(* Logix 5000 project; controller EVR_Heat vendor 1 type 14 code 217 rev 35.11; software revision 35.00 *)

TASK MainTask (continuous, watchdog 500 ms) : MainProgram

MODULES
   Local : vendor 1 type 14 code 217 (5069 0, rev 35.11)
      EVR : ETHERNET-MODULE (Ethernet 192.168.2.50, rev 1.1, Output RPI 10 ms)   // EVR Map Heat
END_MODULES

TYPE ADM_Bits :
STRUCT
   Requested : ADM_Bits_Request;
   Status : ADM_Bits_Status;
END_STRUCT
END_TYPE

TYPE ADM_Bits_Request :
STRUCT
   AcknowledgeSetupValuesChanged : BOOL;
   AcknowledgeCounterValuesChanged : BOOL;
END_STRUCT
END_TYPE

TYPE ADM_Bits_Status :
STRUCT
   SetupValuesChanged : BOOL;
   CounterValuesChanged : BOOL;
END_STRUCT
END_TYPE

TYPE ADM_Time_Date :
STRUCT
   Current : Structer_Date_Time;
   Requested : Structer_Date_Time;
   SendNewTime : BOOL;
   SendNewDate : BOOL;
END_STRUCT
END_TYPE

TYPE Data_Exchange :
STRUCT
   Status : Data_Exchange_Variables;
   Request : Data_Exchange_Variables;
END_STRUCT
END_TYPE

TYPE Data_Exchange_Variables :
STRUCT
   Element : INT;
   Value : DINT;
END_STRUCT
END_TYPE

TYPE Error_LookUp :
STRUCT
   Status : Error_LookUp_Status;
   Request : Error_LookUp_Request;
END_STRUCT
END_TYPE

TYPE Error_LookUp_Request :
STRUCT
   ModuleToLookUp : SINT;
END_STRUCT
END_TYPE

TYPE Error_LookUp_Status :
STRUCT
   Alarms : DINT;
   Deviations : DINT;
   Advisories : DINT;
   LookUpModule : SINT;
   ModuleErrorState : Errors_Module_Booleans;
END_STRUCT
END_TYPE

TYPE Error_Present_Booleans :
STRUCT
   AlarmPresent : BOOL;
   DeviationPresent : BOOL;
   AdvisoriesPresent : BOOL;
END_STRUCT
END_TYPE

TYPE Errors_Module_Booleans :
STRUCT
   RedMcm : Error_Present_Booleans;
   BlueMcm : Error_Present_Booleans;
   RedTank : Error_Present_Booleans;
   BlueTank : Error_Present_Booleans;
   Voltex : Error_Present_Booleans;
END_STRUCT
END_TYPE

TYPE EVR_ADM :
STRUCT
   Bits : ADM_Bits;
   Date_Time : ADM_Time_Date;
END_STRUCT
END_TYPE

TYPE EVR_System :
STRUCT
   Bits : System_Bits;
   ErrorLookUp : Error_LookUp;
   Information : System_Information;
   Recipes : Recipes;
   DataExchange : Data_Exchange;
   HeartbeatMonitoring : Equipment_Heartbeat_Monitoring;
END_STRUCT
END_TYPE

TYPE EVR_Voltex :
STRUCT
   Bits : Voltex_Bits;
END_STRUCT
END_TYPE

TYPE HEAT_Bits_System :
STRUCT
   Status : HEAT_Bits_System_Status;
   Request : HEAT_Bits_System_Requested;
END_STRUCT
END_TYPE

TYPE HEAT_Bits_System_Requested :
STRUCT
   HeatOn : BOOL;
   HeatOff : BOOL;
   HeatSetback : BOOL;
   AcknowledgeClearErrors : BOOL;
   ResetSystemOffReason : BOOL;
   ResetIdleTimer : BOOL;
END_STRUCT
END_TYPE

TYPE HEAT_Bits_System_Status :
STRUCT
   HeartbeatToPlc : BOOL;
   SystemActive : BOOL;   // System On
   ZonesActive : BOOL;   // Zone(s) Active
   ZonesWarmingUp : BOOL;   // Zone(s) Warming Up
   ZonesHeaksoaking : BOOL;   // Zone(s) are Heatsoaking
   ZonesAtTemperature : BOOL;   // All Zone(s) are at Temperature
   ZonesInSetback : BOOL;   // All Zone(s) are in Setback Mode
   NoSystemAlarmsPresent : BOOL;
   NoSystemDeviationsPresent : BOOL;
   NoSystemAdvisoriesPresent : BOOL;
   NoZonesAlarmsPresent : BOOL;   // No Zone(s) Alarms are Present
   NoZonesDeviationsPresent : BOOL;   // No Zone(s) Deviations are Present
   NoZonesAdvisoriesPresent : BOOL;   // No Zone(s) Advisories are Present
   Shutdown : HEAT_Bits_System_Status_Shutdown;   // Reason for heat being shutdown
END_STRUCT
END_TYPE

TYPE HEAT_Bits_System_Status_Shutdown :
STRUCT
   FromADM : BOOL;
   ADMRedKeyPressed : BOOL;
   PumpIdleTimeout : BOOL;
   AlarmDetected : BOOL;
   InternalGracoNetworkLost : BOOL;
   PlcConnectionLost : BOOL;
   PlcRelinquishedControl : BOOL;
END_STRUCT
END_TYPE

TYPE HEAT_Bits_Zone_Enabled_Request :
STRUCT
   Cmd : HEAT_Zone_Struct_BOOL;
   Strobe : BOOL;   // Send to the Heat Controller
   Feedback : HEAT_Setup_Parameters_Feedback;
END_STRUCT
END_TYPE

TYPE HEAT_Bits_Zone_Status :
STRUCT
   Installed : HEAT_Zone_Struct_BOOL;
   Active : HEAT_Zone_Struct_BOOL;   // Heat is On
   AlarmPresent : HEAT_Zone_Struct_BOOL;
END_STRUCT
END_TYPE

TYPE HEAT_Bits_Zones :
STRUCT
   Status : HEAT_Bits_Zone_Status;
END_STRUCT
END_TYPE

TYPE HEAT_Data :
STRUCT
   System : HEAT_System;
   Zone : HEAT_Zone_Information;
   DataExchange : Data_Exchange;
   Errors : HEAT_Errors;
   HeartbeatMonitoring : Equipment_Heartbeat_Monitoring;
END_STRUCT
END_TYPE

TYPE HEAT_Errors :
STRUCT
   System : HEAT_Errors_System;
END_STRUCT
END_TYPE

TYPE HEAT_Errors_System :
STRUCT
   Alarms : DINT;
   Deviations : DINT;
   Advisories : DINT;
END_STRUCT
END_TYPE

TYPE HEAT_Errors_Zone_Struct :
STRUCT
   Alarms : INT;
   Deviations : INT;
   Advisories : INT;
END_STRUCT
END_TYPE

TYPE HEAT_Individual_Zone_Actual_Status :
STRUCT
   State : HEAT_Individual_Zone_Heat_States;
   Temperature : DINT;   // XXX.X deg C
   HeatSoakTimeRemaining : INT;   // XXXX seconds
   CurrentUsage : SINT;   // XX.X Amps
   DutyCycle : SINT;   // XXX %
END_STRUCT
END_TYPE

TYPE HEAT_Individual_Zone_Heat_States :
STRUCT
   WarmingUp : BOOL;
   HeatSoak : BOOL;
   AtTemperature : BOOL;
   Setback : BOOL;
   DeviationAdvisoryPresent : BOOL;
   AlarmPresent : BOOL;
END_STRUCT
END_TYPE

TYPE HEAT_Individual_Zone_Setup_Status :
STRUCT
   ZoneType : SINT;   // 0=HOSE, 1=VALVE, 2=MANIFOLD, 3=PGM, 4=FLOWMETER, 5=PRESS REG, 6=BLANKET, 7=OTHER, 8=MONITOR ONLY
   Setpoint : INT;   // XXX deg C
   Setback : INT;   // XXX deg C
   HeatSoak : SINT;   // XXX minutes
END_STRUCT
END_TYPE

TYPE HEAT_Individual_Zone_Status :
STRUCT
   Setup : HEAT_Individual_Zone_Setup_Status;
   Actual : HEAT_Individual_Zone_Actual_Status;
END_STRUCT
END_TYPE

TYPE HEAT_Information_Status :
STRUCT
   LongestHeatSoakRemaining : INT;   // XXXX seconds
   IdleTimeoutCountdown : INT;   // XXXX seconds
END_STRUCT
END_TYPE

TYPE HEAT_Information_System :
STRUCT
   Status : HEAT_Information_Status;
END_STRUCT
END_TYPE

TYPE HEAT_Information_Zones :
STRUCT
   ActualTemperature : HEAT_Zone_Struct_INT;   // XXXX.X deg C
END_STRUCT
END_TYPE

TYPE HEAT_Setup_Parameters :
STRUCT
   Setpoint : HEAT_Setup_Parameters_INT;
   Setback : HEAT_Setup_Parameters_INT;
   Heatsoak : HEAT_Setup_Parameters_INT;
   Enabled : HEAT_Bits_Zone_Enabled_Request;
END_STRUCT
END_TYPE

TYPE HEAT_Setup_Parameters_Feedback :
STRUCT
   Accepted : BOOL;
   Rejected : BOOL;
END_STRUCT
END_TYPE

TYPE HEAT_Setup_Parameters_INT :
STRUCT
   Feedback : HEAT_Setup_Parameters_Feedback;
   RequestValue : INT;
   Update : HEAT_Zone_Struct_BOOL;
   Strobe : BOOL;   // Send to Heat Controller
END_STRUCT
END_TYPE

TYPE HEAT_System :
STRUCT
   Bits : HEAT_Bits_System;
   Information : HEAT_Information_System;
END_STRUCT
END_TYPE

TYPE HEAT_Zone_Individual_Information :
STRUCT
   Bits : HEAT_Bits_Zones;
   Information : HEAT_Information_Zones;
END_STRUCT
END_TYPE

TYPE HEAT_Zone_Information :
STRUCT
   Information : HEAT_Zone_Individual_Information;
   SetupParameters : HEAT_Setup_Parameters;
   Multiplexer : HEAT_Zone_Multiplexer;
END_STRUCT
END_TYPE

TYPE HEAT_Zone_Multiplexer :
STRUCT
   RequestZone : SINT;
   ZoneInformation : HEAT_Zone_Multiplexer_Information;
END_STRUCT
END_TYPE

TYPE HEAT_Zone_Multiplexer_Information :
STRUCT
   ActiveNumber : SINT;   // Zone information displayed
   State : HEAT_Individual_Zone_Heat_States;
   SoakTimeRemaining : INT;   // XXXX seconds
   CurrentUsage : INT;   // XX.X Amps
   DutyCycle : INT;   // XXX %
   SetpointTemperature : INT;   // XXX deg C
   SetbackTemperature : INT;   // XXX deg C
   HeatSoakSetTime : SINT;   // XXX minutes
   Profile : SINT;   // 0 = Hose 1 = Valve 2 = Manifold 3 = PGM 4 = Flowmeter 5= Press Reg
   Alarms : INT;
   Deviations : INT;
   Advisories : INT;
END_STRUCT
END_TYPE

TYPE HEAT_Zone_Struct_BOOL :
STRUCT
   Zone1 : BOOL;
   Zone2 : BOOL;
   Zone3 : BOOL;
   Zone4 : BOOL;
   Zone5 : BOOL;
   Zone6 : BOOL;
   Zone7 : BOOL;
   Zone8 : BOOL;
   Zone9 : BOOL;
   Zone10 : BOOL;
   Zone11 : BOOL;
   Zone12 : BOOL;
   Zone13 : BOOL;
   Zone14 : BOOL;
   Zone15 : BOOL;
   Zone16 : BOOL;
END_STRUCT
END_TYPE

TYPE HEAT_Zone_Struct_INT :
STRUCT
   Zone1 : INT;
   Zone2 : INT;
   Zone3 : INT;
   Zone4 : INT;
   Zone5 : INT;
   Zone6 : INT;
   Zone7 : INT;
   Zone8 : INT;
   Zone9 : INT;
   Zone10 : INT;
   Zone11 : INT;
   Zone12 : INT;
   Zone13 : INT;
   Zone14 : INT;
   Zone15 : INT;
   Zone16 : INT;
END_STRUCT
END_TYPE

TYPE Recipe_Active_Status :
STRUCT
   AmountDispensed : DINT;   // XXXX.XX cc
   ShotSize : DINT;   // XXXX.XX cc
   Flowrate : INT;   // XXXX.XX cc/sec
   ShotCalibartion : INT;   // -/+ XX.XX cc
   DispenseType : SINT;   // 0=operator, 1=shot
   ShotTimeRemaining : INT;   // XXXX.X seconds
   Recipe : SINT;
END_STRUCT
END_TYPE

TYPE Recipe_Gateway_Request :
STRUCT
   Flowrate : INT;   // XXX.XX cc/sec
   ShotSize : DINT;   // XXXX.XX cc
   DispenseType : SINT;   // 0 = operator, 1 = shot
   Recipe : SINT;
END_STRUCT
END_TYPE

TYPE Recipe_Lookup :
STRUCT
   Request : Recipe_Lookup_Request;
   Status : Recipe_Lookup_Status;
END_STRUCT
END_TYPE

TYPE Recipe_Lookup_Request :
STRUCT
   LookUpRecipe : SINT;
END_STRUCT
END_TYPE

TYPE Recipe_Lookup_Status :
STRUCT
   ActiveNumber : SINT;
   ShotSize : DINT;   // XXXX.XX cc
   Flowrate : INT;   // XXX.XX cc/sec
   Calibration : INT;   // -/+ XX.XX cc
   DipsenseType : SINT;   // 0=operator, 1=shot
END_STRUCT
END_TYPE

TYPE Recipes :
STRUCT
   Active : Recipe_Active_Status;
   Gateway : Recipe_Gateway_Request;
   Lookup : Recipe_Lookup;
END_STRUCT
END_TYPE

TYPE Structer_Date :   // Will house the information for the date
STRUCT
   Month : SINT;
   Year : SINT;
   Day : SINT;
END_STRUCT
END_TYPE

TYPE Structer_Date_Time :   // Will house the information for the date & time in military time
STRUCT
   Date : Structer_Date;
   Time : Structer_Time;
END_STRUCT
END_TYPE

TYPE Structer_Tank_Levels :
STRUCT
   Unknown : BOOL;
   Low : BOOL;
   Middle : BOOL;
   High : BOOL;
END_STRUCT
END_TYPE

TYPE Structer_Time :   // Will house the information for the time in Military Time
STRUCT
   Hours : SINT;
   Minutes : SINT;
   Seconds : SINT;
END_STRUCT
END_TYPE

TYPE System :
STRUCT
   EVR : EVR_System;
   ADM : EVR_ADM;
   Voltex : EVR_Voltex;
   Tanks : TankStands;
   Heat : HEAT_Data;
END_STRUCT
END_TYPE

TYPE System_Bits :
STRUCT
   Status : System_Bits_Status;
   Requested : System_Bits_Request;
END_STRUCT
END_TYPE

TYPE System_Bits_Request :
STRUCT
   SystemEnable : BOOL;
   PLCLockout : BOOL;
   OperatorShotDispense : BOOL;
   CancelShot : BOOL;
   Purge : BOOL;
   BasePurge : BOOL;
   Depressurization : BOOL;
   Park : BOOL;
   AcknowledgeAllErrors : BOOL;
   GatewayRecipeLockout : BOOL;
   CancelGelShot : BOOL;
   Recirculation : BOOL;
END_STRUCT
END_TYPE

TYPE System_Bits_Status :
STRUCT
   HeartbeatToPLC : BOOL;
   SystemOn : BOOL;
   PlcLockoutIsActive : BOOL;
   SystemReady : BOOL;
   NoSystemAlarmsPresent : BOOL;
   NoSystemDeviationsPresent : BOOL;
   NoSystemAdvisoriesPresent : BOOL;
   RecipeIsDispensing : BOOL;
   DispenseValveIsOpened : BOOL;
   SystemIsPurging : BOOL;
   SystemIsBasePurging : BOOL;
   SystemIsDepressurizing : BOOL;
   SystemIsParking : BOOL;
   SystemIsParked : BOOL;
   RecipeIsValid : BOOL;
   GaetwayRecipeLockoutActive : BOOL;
   GelShotIsDispensing : BOOL;
   GelShotIsAlarming : BOOL;
   SystemIsRecirculating : BOOL;
   DispenseValveIsOpen : Valves;
   AutoRecirculationValvesIsOpen : Valves;
END_STRUCT
END_TYPE

TYPE System_Information :
STRUCT
   Request : System_Information_Request;
   Status : System_Information_Status;
END_STRUCT
END_TYPE

TYPE System_Information_Request :
STRUCT
   Ratio : INT;   // XX.XX : 1.00
   RatioOffset : INT;   // -/+XX.XX
END_STRUCT
END_TYPE

TYPE System_Information_Status :
STRUCT
   OuletPressure_Red : INT;   // XX.XX bar
   OutletPressure_Blue : INT;   // XX.XX bar
   InletPressure_Red : INT;   // XX.XX bar
   InletPressure_Blue : INT;   // XX.XX bar
   Ratio : INT;   // XX.XX : 1.00
   RatioOffset : INT;   // -/+ XX.XX
   CombinedFlow : INT;   // XX.XX cc/sec
   GelTimeRemainingBeforeShot : INT;   // XXXX seconds
   RecirculationTimeRemaining : INT;   // XXXX seconds
END_STRUCT
END_TYPE

TYPE TanksStands_Individual :
STRUCT
   Request : TankStand_Bits_Request;
   Status : TankStand_Bits_Status;
END_STRUCT
END_TYPE

TYPE TankStand_Bits :
STRUCT
   Request : TankStand_Bits_Request;
   Status : TankStand_Bits_Status;
END_STRUCT
END_TYPE

TYPE TankStand_Bits_Request :
STRUCT
   Fill : BOOL;
END_STRUCT
END_TYPE

TYPE TankStand_Bits_Status :
STRUCT
   IsFilling : BOOL;
   Levels : Structer_Tank_Levels;
END_STRUCT
END_TYPE

TYPE TankStands :
STRUCT
   Red : TanksStands_Individual;
   Blue : TanksStands_Individual;
END_STRUCT
END_TYPE

TYPE Valves :
STRUCT
   A : BOOL;
   B : BOOL;
END_STRUCT
END_TYPE

TYPE Voltex_Bits :
STRUCT
   Request : Voltex_Bits_Request;
   Status : Voltex_Bits_Status;
END_STRUCT
END_TYPE

TYPE Voltex_Bits_Request :
STRUCT
   MotorOn : BOOL;
   AirInjectionOpen : BOOL;
END_STRUCT
END_TYPE

TYPE Voltex_Bits_Status :
STRUCT
   MotorIsRunning : BOOL;
   DispenseWaitingSpeedReached : BOOL;
   AtTargetSpeed : BOOL;
   AirInjectionValveOpen : BOOL;
END_STRUCT
END_TYPE

ADD_ON_INSTRUCTION Equipment_Heartbeat_Monitoring   (* revision 1.0, vendor Graco *)
// This logic will monitoring for the heatbeat, if it is gone for a specific amount of time, then set an disconnect bit
VAR_INPUT
   EquipmentHeartbeat : BOOL; {access None, required}   // Is the actual status of the heartbeat that is being monitored
END_VAR
VAR_OUTPUT
   EquipmentDisconnected : BOOL; {access None, visible}   // Lets the world outside the function know that the equipment is offline
END_VAR
VAR_INPUT
   OfflineTimeout : ALIAS FOR ElapsedTime_Timer.PRE; {access None, required}   // XXXX ms
   StopMonitoringTimer : BOOL; {access None, required}   // Variable that can be used to stop the heartbeat logic from erroring out
END_VAR
VAR
   LowSideMonitor_Counter : COUNTER; {access None}
   HighSideMonitor_Counter : COUNTER; {access None}
   HeartbeatFailiure : BOOL; {access None}
   ElapsedTime_Timer : TIMER; {access None}
END_VAR

ROUTINE Logic   (* ladder *)
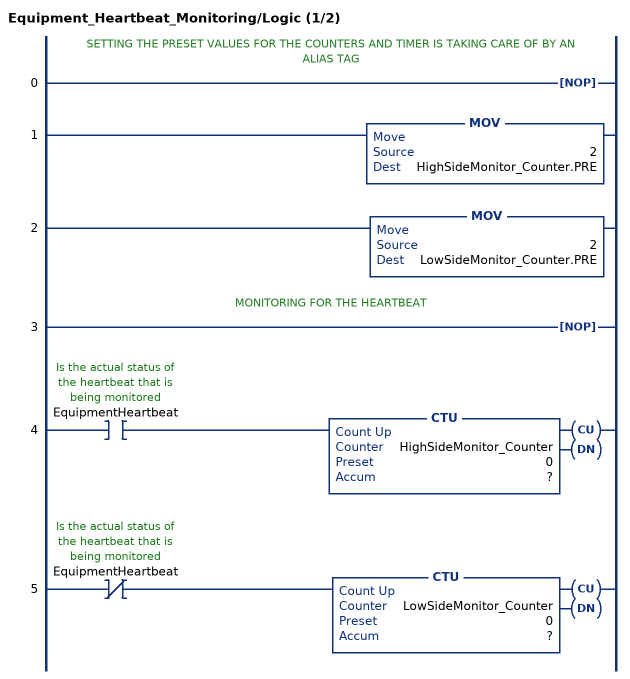
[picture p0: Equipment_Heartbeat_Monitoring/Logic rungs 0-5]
   // SETTING THE PRESET VALUES FOR THE COUNTERS AND TIMER IS TAKING CARE OF BY AN ALIAS TAG
   0: NOP();
   1: MOV(2,HighSideMonitor_Counter.PRE);
   2: MOV(2,LowSideMonitor_Counter.PRE);
   // MONITORING FOR THE HEARTBEAT
   3: NOP();
   4: XIC(EquipmentHeartbeat)CTU(HighSideMonitor_Counter,?,?);
   5: XIO(EquipmentHeartbeat)CTU(LowSideMonitor_Counter,?,?);
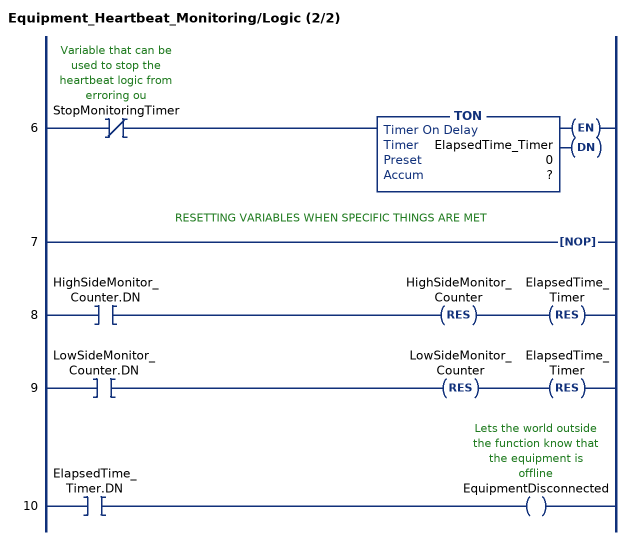
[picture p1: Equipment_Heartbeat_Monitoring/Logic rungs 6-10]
   6: XIO(StopMonitoringTimer)TON(ElapsedTime_Timer,?,?);
   // RESETTING VARIABLES WHEN SPECIFIC THINGS ARE MET
   7: NOP();
   8: XIC(HighSideMonitor_Counter.DN)RES(HighSideMonitor_Counter)RES(ElapsedTime_Timer);
   9: XIC(LowSideMonitor_Counter.DN)RES(LowSideMonitor_Counter)RES(ElapsedTime_Timer);
   10: XIC(ElapsedTime_Timer.DN)OTE(EquipmentDisconnected);
END_ROUTINE
END_ADD_ON_INSTRUCTION

VAR_GLOBAL   (* controller tags *)
   EVR_System_Data : System;
        .Heat.Zone.Multiplexer.ZoneInformation.Alarms.3   // T8A_
        .Heat.Errors.System.Alarms.10   // CCFX
        .Heat.Zone.Multiplexer.ZoneInformation.Alarms.0   // T4A_
        .Heat.Errors.System.Deviations.5   // T9TX
        .Heat.Errors.System.Alarms.0   // CBH1
        .Heat.Zone.Multiplexer.ZoneInformation.Alarms.1   // T4A_
        .Heat.Zone.Multiplexer.ZoneInformation.Alarms.2   // T1A_
        .Heat.Zone.Multiplexer.ZoneInformation.Alarms.4   // T9A_
        .Heat.Zone.Multiplexer.ZoneInformation.Alarms.5   // A4A_
        .Heat.Errors.System.Alarms.11   // V6H1
        .Heat.Errors.System.Alarms.1   // CBH2
        .Heat.Errors.System.Alarms.12   // V4H1
        .Heat.Errors.System.Alarms.9   // CBGX
        .Heat.Errors.System.Alarms.8   // CABX
        .Heat.Errors.System.Alarms.14   // T4TX
        .Heat.Errors.System.Alarms.20   // V6H2
        .Heat.Zone.Multiplexer.ZoneInformation.Alarms.6   // A1A_
        .Heat.Errors.System.Advisories.0   // MGFX
        .Heat.Zone.Multiplexer.ZoneInformation.Alarms.7   // A8A_
        .Heat.Errors.System.Deviations.1   // V2H1
        .Heat.Zone.Multiplexer.ZoneInformation.Alarms.8   // A7A_
        .Heat.Errors.System.Alarms.21   // V4H2
        .Heat.Zone.Multiplexer.ZoneInformation.Alarms.9   // T6A_
        .Heat.Errors.System.Deviations.17   // V2H2
        .Heat.Zone.Multiplexer.ZoneInformation.Advisories.0   // T3A_
        .Heat.Errors.System.Deviations.2   // A2VX
        .Heat.Errors.System.Deviations.3   // A3VX
        .Heat.Zone.Multiplexer.ZoneInformation.Advisories.1   // T3A_
        .Heat.Zone.Multiplexer.ZoneInformation.Advisories.2   // T2A_
        .Heat.Zone.Multiplexer.ZoneInformation.Advisories.4   // A3A_
        .Heat.Errors.System.Deviations.4   // T3TX
        .Heat.Zone.Multiplexer.ZoneInformation.Advisories.5   // A2A_
        .Heat.Errors.System.Deviations.6   // T6TX
END_VAR

PROGRAM MainProgram   (* main routine MainRoutine *)

ROUTINE EVR_Inputs   (* ladder *)
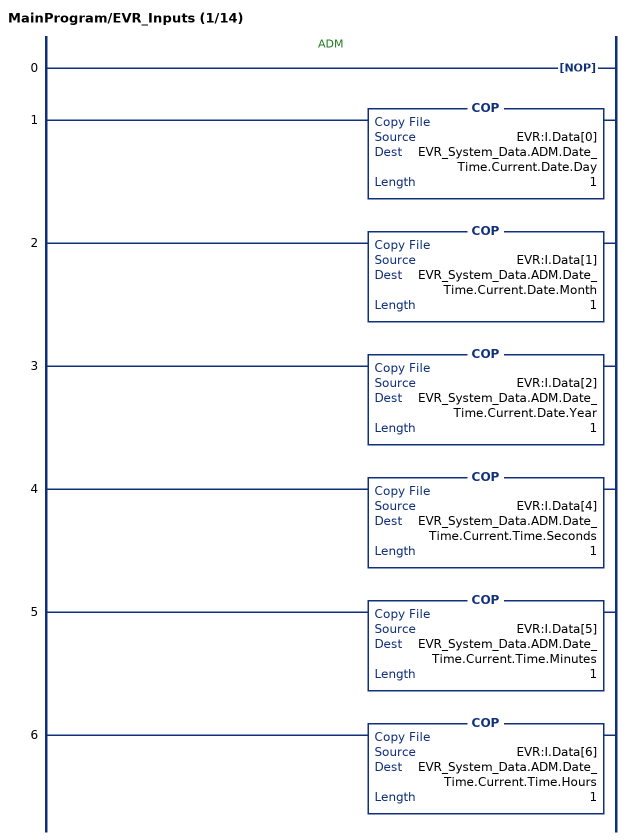
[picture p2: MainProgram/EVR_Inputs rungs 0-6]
   // ADM
   0: NOP();
   1: COP(EVR:I.Data[0],EVR_System_Data.ADM.Date_Time.Current.Date.Day,1);
   2: COP(EVR:I.Data[1],EVR_System_Data.ADM.Date_Time.Current.Date.Month,1);
   3: COP(EVR:I.Data[2],EVR_System_Data.ADM.Date_Time.Current.Date.Year,1);
   4: COP(EVR:I.Data[4],EVR_System_Data.ADM.Date_Time.Current.Time.Seconds,1);
   5: COP(EVR:I.Data[5],EVR_System_Data.ADM.Date_Time.Current.Time.Minutes,1);
   6: COP(EVR:I.Data[6],EVR_System_Data.ADM.Date_Time.Current.Time.Hours,1);
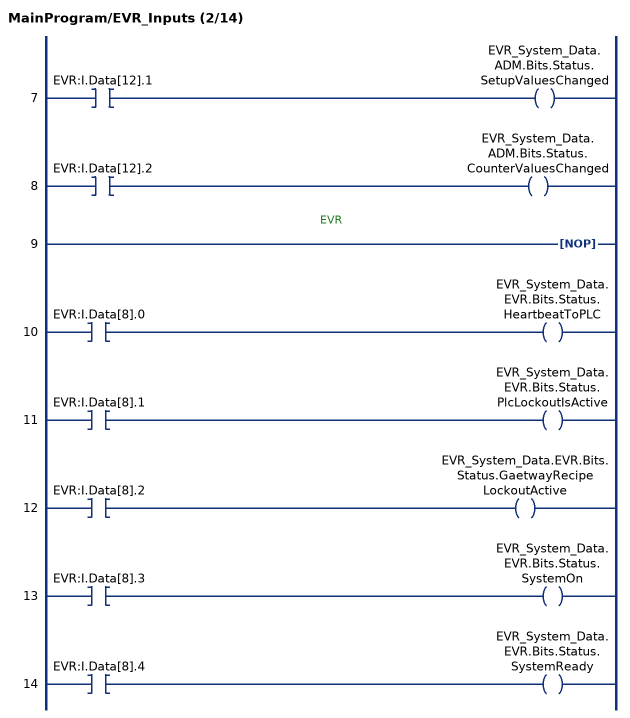
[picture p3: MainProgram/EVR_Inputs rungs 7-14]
   7: XIC(EVR:I.Data[12].1)OTE(EVR_System_Data.ADM.Bits.Status.SetupValuesChanged);
   8: XIC(EVR:I.Data[12].2)OTE(EVR_System_Data.ADM.Bits.Status.CounterValuesChanged);
   // EVR
   9: NOP();
   10: XIC(EVR:I.Data[8].0)OTE(EVR_System_Data.EVR.Bits.Status.HeartbeatToPLC);
   11: XIC(EVR:I.Data[8].1)OTE(EVR_System_Data.EVR.Bits.Status.PlcLockoutIsActive);
   12: XIC(EVR:I.Data[8].2)OTE(EVR_System_Data.EVR.Bits.Status.GaetwayRecipeLockoutActive);
   13: XIC(EVR:I.Data[8].3)OTE(EVR_System_Data.EVR.Bits.Status.SystemOn);
   14: XIC(EVR:I.Data[8].4)OTE(EVR_System_Data.EVR.Bits.Status.SystemReady);
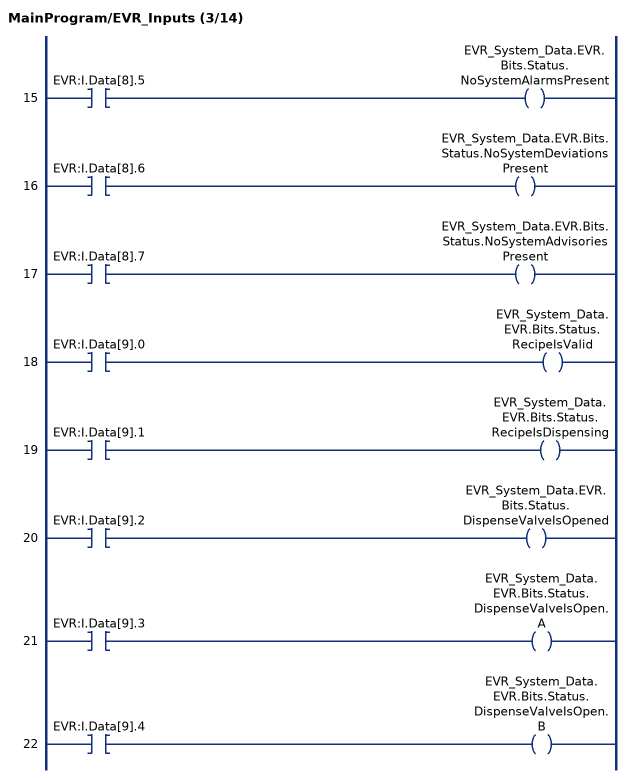
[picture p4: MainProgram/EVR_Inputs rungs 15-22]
   15: XIC(EVR:I.Data[8].5)OTE(EVR_System_Data.EVR.Bits.Status.NoSystemAlarmsPresent);
   16: XIC(EVR:I.Data[8].6)OTE(EVR_System_Data.EVR.Bits.Status.NoSystemDeviationsPresent);
   17: XIC(EVR:I.Data[8].7)OTE(EVR_System_Data.EVR.Bits.Status.NoSystemAdvisoriesPresent);
   18: XIC(EVR:I.Data[9].0)OTE(EVR_System_Data.EVR.Bits.Status.RecipeIsValid);
   19: XIC(EVR:I.Data[9].1)OTE(EVR_System_Data.EVR.Bits.Status.RecipeIsDispensing);
   20: XIC(EVR:I.Data[9].2)OTE(EVR_System_Data.EVR.Bits.Status.DispenseValveIsOpened);
   21: XIC(EVR:I.Data[9].3)OTE(EVR_System_Data.EVR.Bits.Status.DispenseValveIsOpen.A);
   22: XIC(EVR:I.Data[9].4)OTE(EVR_System_Data.EVR.Bits.Status.DispenseValveIsOpen.B);
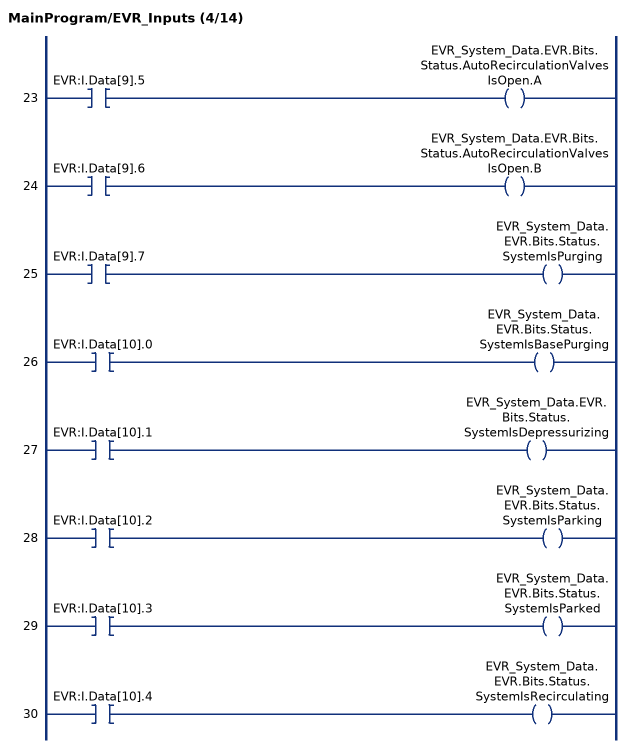
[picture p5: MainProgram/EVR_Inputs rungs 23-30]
   23: XIC(EVR:I.Data[9].5)OTE(EVR_System_Data.EVR.Bits.Status.AutoRecirculationValvesIsOpen.A);
   24: XIC(EVR:I.Data[9].6)OTE(EVR_System_Data.EVR.Bits.Status.AutoRecirculationValvesIsOpen.B);
   25: XIC(EVR:I.Data[9].7)OTE(EVR_System_Data.EVR.Bits.Status.SystemIsPurging);
   26: XIC(EVR:I.Data[10].0)OTE(EVR_System_Data.EVR.Bits.Status.SystemIsBasePurging);
   27: XIC(EVR:I.Data[10].1)OTE(EVR_System_Data.EVR.Bits.Status.SystemIsDepressurizing);
   28: XIC(EVR:I.Data[10].2)OTE(EVR_System_Data.EVR.Bits.Status.SystemIsParking);
   29: XIC(EVR:I.Data[10].3)OTE(EVR_System_Data.EVR.Bits.Status.SystemIsParked);
   30: XIC(EVR:I.Data[10].4)OTE(EVR_System_Data.EVR.Bits.Status.SystemIsRecirculating);
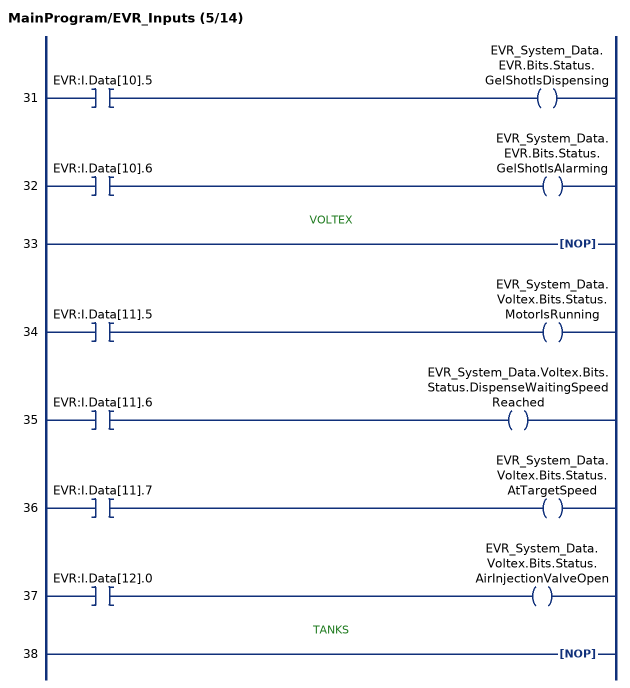
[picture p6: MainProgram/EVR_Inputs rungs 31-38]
   31: XIC(EVR:I.Data[10].5)OTE(EVR_System_Data.EVR.Bits.Status.GelShotIsDispensing);
   32: XIC(EVR:I.Data[10].6)OTE(EVR_System_Data.EVR.Bits.Status.GelShotIsAlarming);
   // VOLTEX
   33: NOP();
   34: XIC(EVR:I.Data[11].5)OTE(EVR_System_Data.Voltex.Bits.Status.MotorIsRunning);
   35: XIC(EVR:I.Data[11].6)OTE(EVR_System_Data.Voltex.Bits.Status.DispenseWaitingSpeedReached);
   36: XIC(EVR:I.Data[11].7)OTE(EVR_System_Data.Voltex.Bits.Status.AtTargetSpeed);
   37: XIC(EVR:I.Data[12].0)OTE(EVR_System_Data.Voltex.Bits.Status.AirInjectionValveOpen);
   // TANKS
   38: NOP();
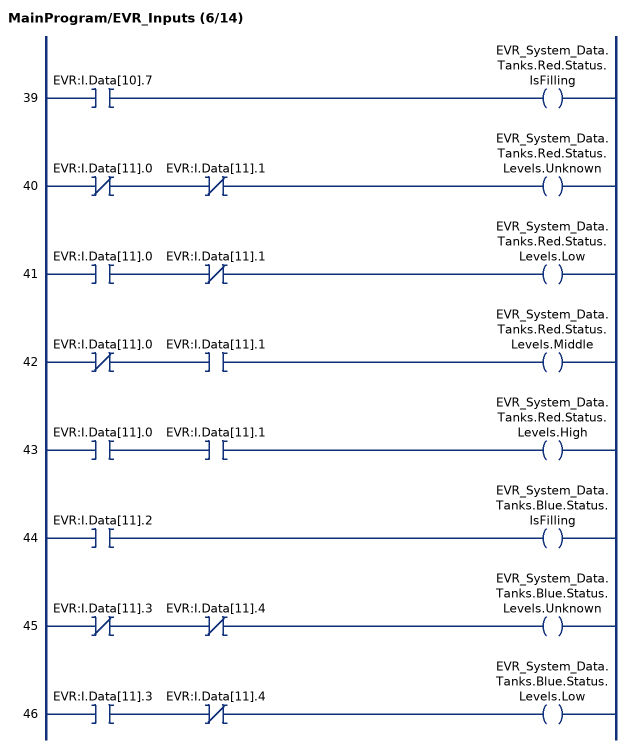
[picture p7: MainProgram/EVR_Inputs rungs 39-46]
   39: XIC(EVR:I.Data[10].7)OTE(EVR_System_Data.Tanks.Red.Status.IsFilling);
   40: XIO(EVR:I.Data[11].0)XIO(EVR:I.Data[11].1)OTE(EVR_System_Data.Tanks.Red.Status.Levels.Unknown);
   41: XIC(EVR:I.Data[11].0)XIO(EVR:I.Data[11].1)OTE(EVR_System_Data.Tanks.Red.Status.Levels.Low);
   42: XIO(EVR:I.Data[11].0)XIC(EVR:I.Data[11].1)OTE(EVR_System_Data.Tanks.Red.Status.Levels.Middle);
   43: XIC(EVR:I.Data[11].0)XIC(EVR:I.Data[11].1)OTE(EVR_System_Data.Tanks.Red.Status.Levels.High);
   44: XIC(EVR:I.Data[11].2)OTE(EVR_System_Data.Tanks.Blue.Status.IsFilling);
   45: XIO(EVR:I.Data[11].3)XIO(EVR:I.Data[11].4)OTE(EVR_System_Data.Tanks.Blue.Status.Levels.Unknown);
   46: XIC(EVR:I.Data[11].3)XIO(EVR:I.Data[11].4)OTE(EVR_System_Data.Tanks.Blue.Status.Levels.Low);
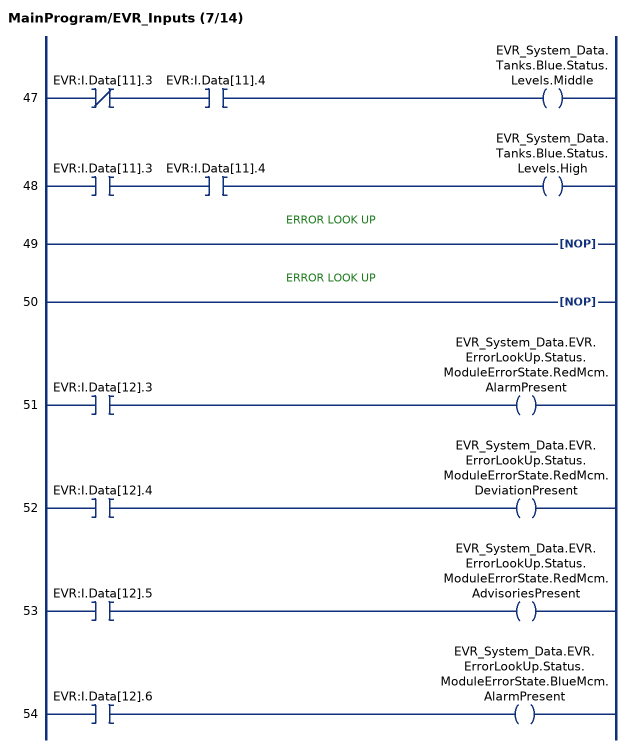
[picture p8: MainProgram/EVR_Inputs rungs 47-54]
   47: XIO(EVR:I.Data[11].3)XIC(EVR:I.Data[11].4)OTE(EVR_System_Data.Tanks.Blue.Status.Levels.Middle);
   48: XIC(EVR:I.Data[11].3)XIC(EVR:I.Data[11].4)OTE(EVR_System_Data.Tanks.Blue.Status.Levels.High);
   // ERROR LOOK UP
   49: NOP();
   // ERROR LOOK UP
   50: NOP();
   51: XIC(EVR:I.Data[12].3)OTE(EVR_System_Data.EVR.ErrorLookUp.Status.ModuleErrorState.RedMcm.AlarmPresent);
   52: XIC(EVR:I.Data[12].4)OTE(EVR_System_Data.EVR.ErrorLookUp.Status.ModuleErrorState.RedMcm.DeviationPresent);
   53: XIC(EVR:I.Data[12].5)OTE(EVR_System_Data.EVR.ErrorLookUp.Status.ModuleErrorState.RedMcm.AdvisoriesPresent);
   54: XIC(EVR:I.Data[12].6)OTE(EVR_System_Data.EVR.ErrorLookUp.Status.ModuleErrorState.BlueMcm.AlarmPresent);
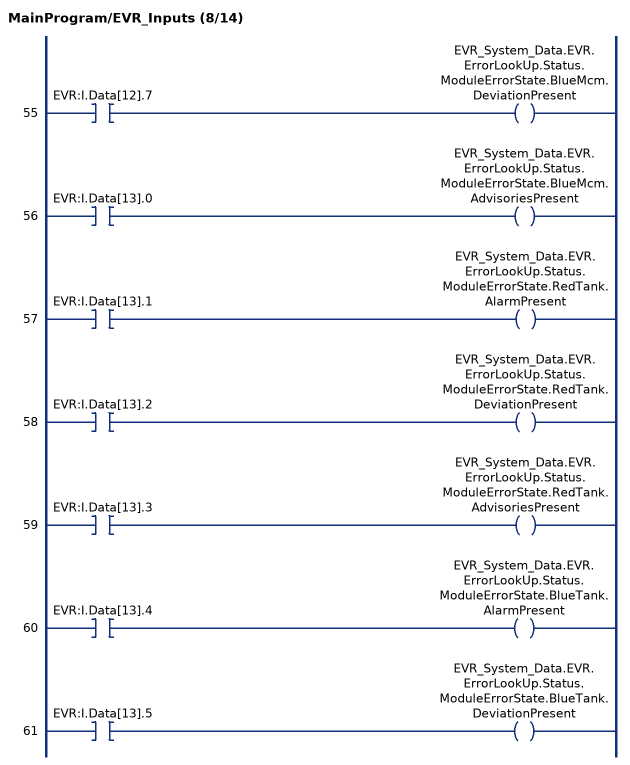
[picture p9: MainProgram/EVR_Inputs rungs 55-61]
   55: XIC(EVR:I.Data[12].7)OTE(EVR_System_Data.EVR.ErrorLookUp.Status.ModuleErrorState.BlueMcm.DeviationPresent);
   56: XIC(EVR:I.Data[13].0)OTE(EVR_System_Data.EVR.ErrorLookUp.Status.ModuleErrorState.BlueMcm.AdvisoriesPresent);
   57: XIC(EVR:I.Data[13].1)OTE(EVR_System_Data.EVR.ErrorLookUp.Status.ModuleErrorState.RedTank.AlarmPresent);
   58: XIC(EVR:I.Data[13].2)OTE(EVR_System_Data.EVR.ErrorLookUp.Status.ModuleErrorState.RedTank.DeviationPresent);
   59: XIC(EVR:I.Data[13].3)OTE(EVR_System_Data.EVR.ErrorLookUp.Status.ModuleErrorState.RedTank.AdvisoriesPresent);
   60: XIC(EVR:I.Data[13].4)OTE(EVR_System_Data.EVR.ErrorLookUp.Status.ModuleErrorState.BlueTank.AlarmPresent);
   61: XIC(EVR:I.Data[13].5)OTE(EVR_System_Data.EVR.ErrorLookUp.Status.ModuleErrorState.BlueTank.DeviationPresent);
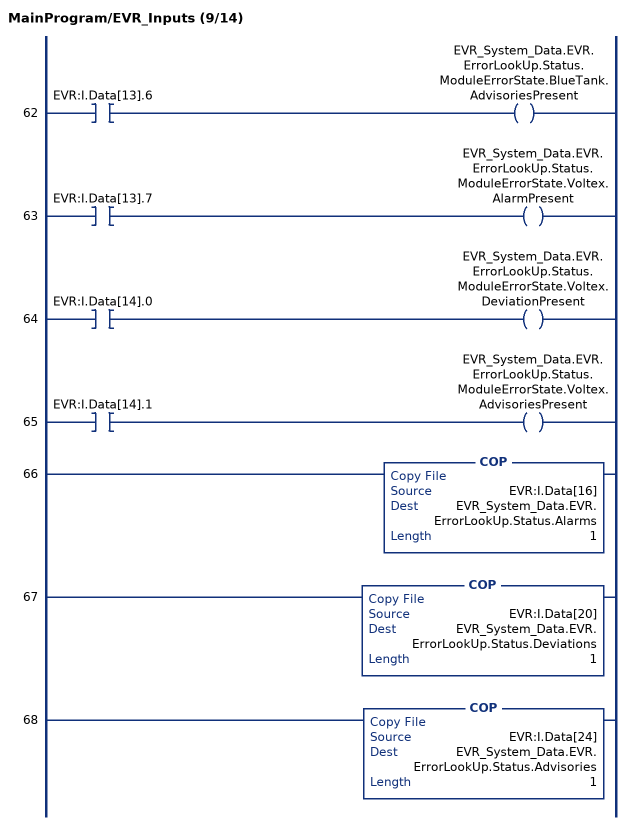
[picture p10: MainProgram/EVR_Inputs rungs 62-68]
   62: XIC(EVR:I.Data[13].6)OTE(EVR_System_Data.EVR.ErrorLookUp.Status.ModuleErrorState.BlueTank.AdvisoriesPresent);
   63: XIC(EVR:I.Data[13].7)OTE(EVR_System_Data.EVR.ErrorLookUp.Status.ModuleErrorState.Voltex.AlarmPresent);
   64: XIC(EVR:I.Data[14].0)OTE(EVR_System_Data.EVR.ErrorLookUp.Status.ModuleErrorState.Voltex.DeviationPresent);
   65: XIC(EVR:I.Data[14].1)OTE(EVR_System_Data.EVR.ErrorLookUp.Status.ModuleErrorState.Voltex.AdvisoriesPresent);
   66: COP(EVR:I.Data[16],EVR_System_Data.EVR.ErrorLookUp.Status.Alarms,1);
   67: COP(EVR:I.Data[20],EVR_System_Data.EVR.ErrorLookUp.Status.Deviations,1);
   68: COP(EVR:I.Data[24],EVR_System_Data.EVR.ErrorLookUp.Status.Advisories,1);
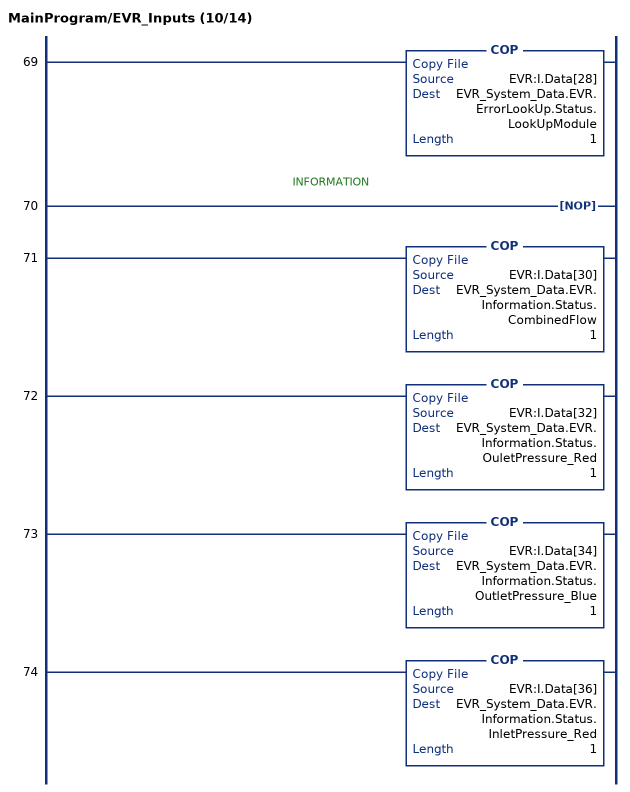
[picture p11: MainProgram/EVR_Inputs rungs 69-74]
   69: COP(EVR:I.Data[28],EVR_System_Data.EVR.ErrorLookUp.Status.LookUpModule,1);
   // INFORMATION
   70: NOP();
   71: COP(EVR:I.Data[30],EVR_System_Data.EVR.Information.Status.CombinedFlow,1);
   72: COP(EVR:I.Data[32],EVR_System_Data.EVR.Information.Status.OuletPressure_Red,1);
   73: COP(EVR:I.Data[34],EVR_System_Data.EVR.Information.Status.OutletPressure_Blue,1);
   74: COP(EVR:I.Data[36],EVR_System_Data.EVR.Information.Status.InletPressure_Red,1);
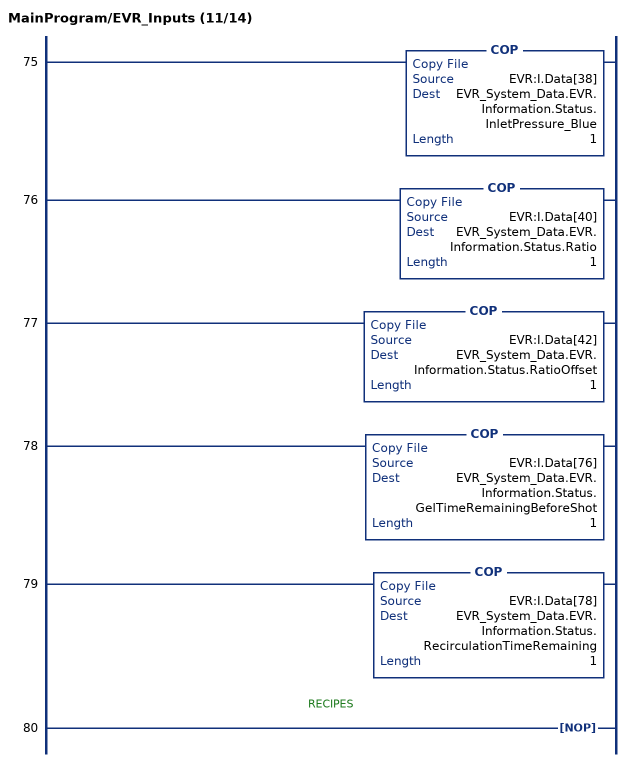
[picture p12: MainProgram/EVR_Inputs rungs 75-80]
   75: COP(EVR:I.Data[38],EVR_System_Data.EVR.Information.Status.InletPressure_Blue,1);
   76: COP(EVR:I.Data[40],EVR_System_Data.EVR.Information.Status.Ratio,1);
   77: COP(EVR:I.Data[42],EVR_System_Data.EVR.Information.Status.RatioOffset,1);
   78: COP(EVR:I.Data[76],EVR_System_Data.EVR.Information.Status.GelTimeRemainingBeforeShot,1);
   79: COP(EVR:I.Data[78],EVR_System_Data.EVR.Information.Status.RecirculationTimeRemaining,1);
   // RECIPES
   80: NOP();
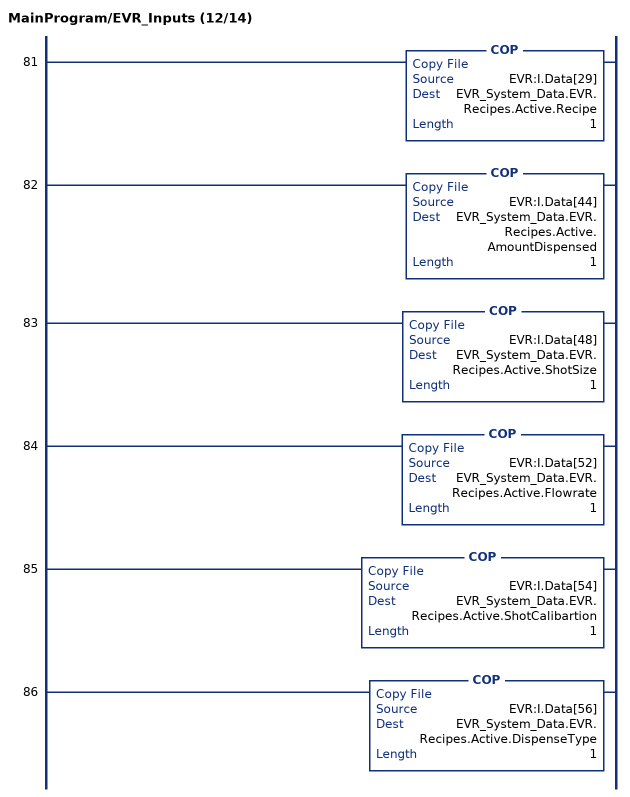
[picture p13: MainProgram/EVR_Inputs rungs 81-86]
   81: COP(EVR:I.Data[29],EVR_System_Data.EVR.Recipes.Active.Recipe,1);
   82: COP(EVR:I.Data[44],EVR_System_Data.EVR.Recipes.Active.AmountDispensed,1);
   83: COP(EVR:I.Data[48],EVR_System_Data.EVR.Recipes.Active.ShotSize,1);
   84: COP(EVR:I.Data[52],EVR_System_Data.EVR.Recipes.Active.Flowrate,1);
   85: COP(EVR:I.Data[54],EVR_System_Data.EVR.Recipes.Active.ShotCalibartion,1);
   86: COP(EVR:I.Data[56],EVR_System_Data.EVR.Recipes.Active.DispenseType,1);
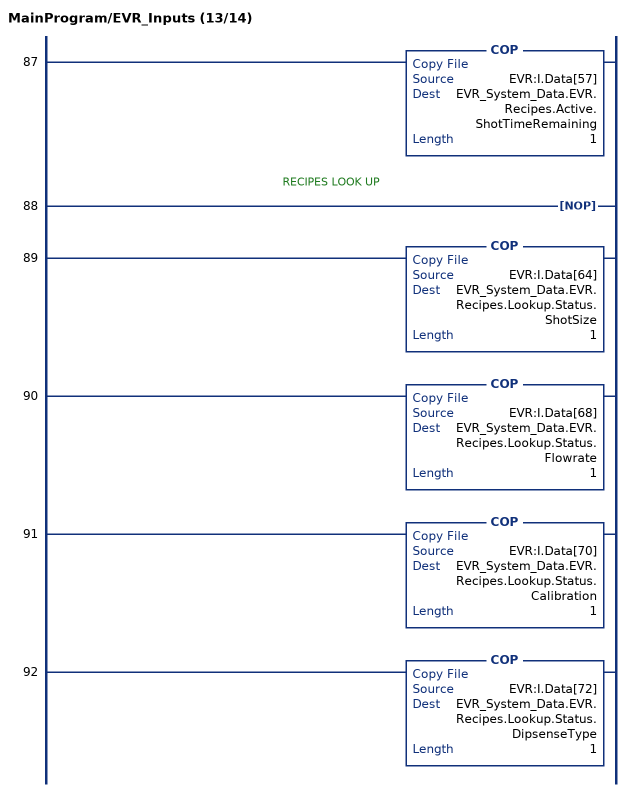
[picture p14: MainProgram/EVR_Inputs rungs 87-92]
   87: COP(EVR:I.Data[57],EVR_System_Data.EVR.Recipes.Active.ShotTimeRemaining,1);
   // RECIPES LOOK UP
   88: NOP();
   89: COP(EVR:I.Data[64],EVR_System_Data.EVR.Recipes.Lookup.Status.ShotSize,1);
   90: COP(EVR:I.Data[68],EVR_System_Data.EVR.Recipes.Lookup.Status.Flowrate,1);
   91: COP(EVR:I.Data[70],EVR_System_Data.EVR.Recipes.Lookup.Status.Calibration,1);
   92: COP(EVR:I.Data[72],EVR_System_Data.EVR.Recipes.Lookup.Status.DipsenseType,1);
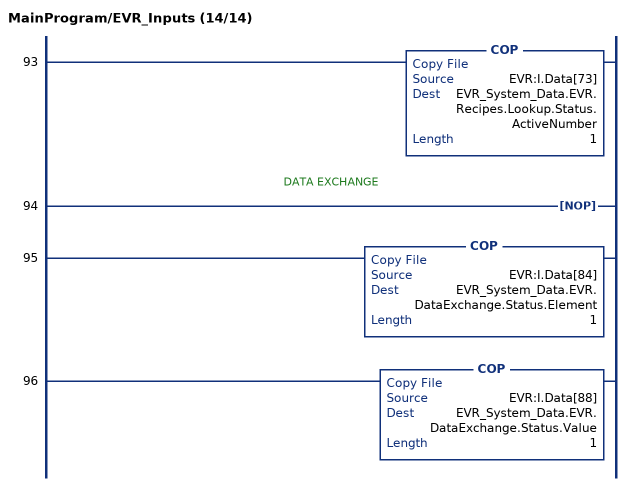
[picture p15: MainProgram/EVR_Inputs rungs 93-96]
   93: COP(EVR:I.Data[73],EVR_System_Data.EVR.Recipes.Lookup.Status.ActiveNumber,1);
   // DATA EXCHANGE
   94: NOP();
   95: COP(EVR:I.Data[84],EVR_System_Data.EVR.DataExchange.Status.Element,1);
   96: COP(EVR:I.Data[88],EVR_System_Data.EVR.DataExchange.Status.Value,1);
END_ROUTINE

ROUTINE EVR_Outputs   (* ladder *)
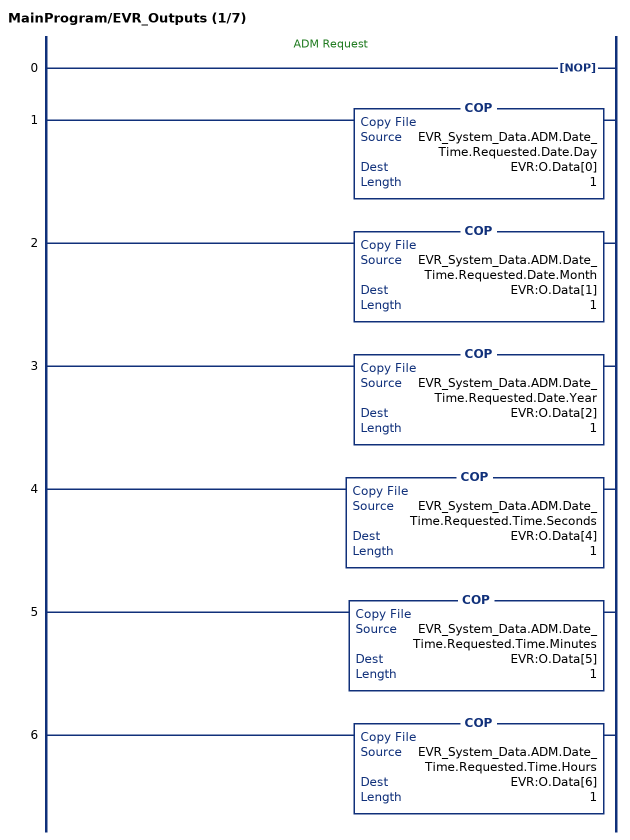
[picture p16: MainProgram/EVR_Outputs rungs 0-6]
   // ADM Request
   0: NOP();
   1: COP(EVR_System_Data.ADM.Date_Time.Requested.Date.Day,EVR:O.Data[0],1);
   2: COP(EVR_System_Data.ADM.Date_Time.Requested.Date.Month,EVR:O.Data[1],1);
   3: COP(EVR_System_Data.ADM.Date_Time.Requested.Date.Year,EVR:O.Data[2],1);
   4: COP(EVR_System_Data.ADM.Date_Time.Requested.Time.Seconds,EVR:O.Data[4],1);
   5: COP(EVR_System_Data.ADM.Date_Time.Requested.Time.Minutes,EVR:O.Data[5],1);
   6: COP(EVR_System_Data.ADM.Date_Time.Requested.Time.Hours,EVR:O.Data[6],1);
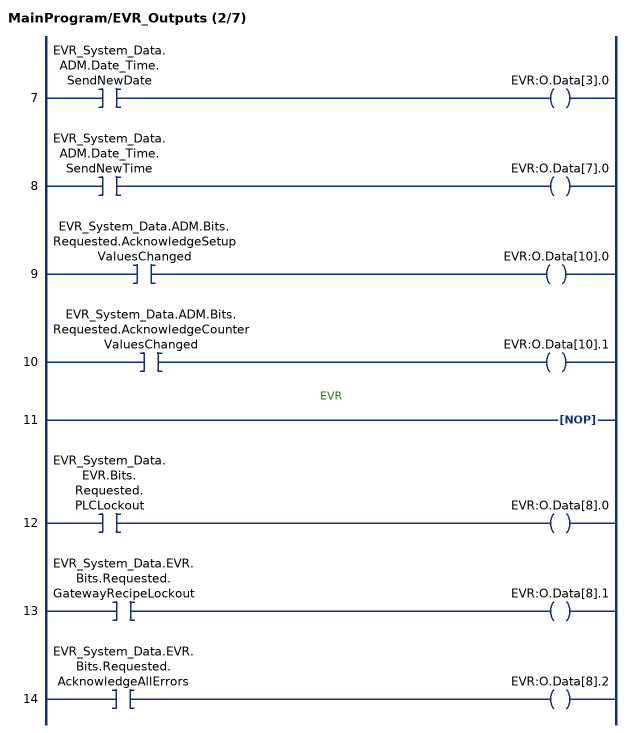
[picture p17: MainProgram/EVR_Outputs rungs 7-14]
   7: XIC(EVR_System_Data.ADM.Date_Time.SendNewDate)OTE(EVR:O.Data[3].0);
   8: XIC(EVR_System_Data.ADM.Date_Time.SendNewTime)OTE(EVR:O.Data[7].0);
   9: XIC(EVR_System_Data.ADM.Bits.Requested.AcknowledgeSetupValuesChanged)OTE(EVR:O.Data[10].0);
   10: XIC(EVR_System_Data.ADM.Bits.Requested.AcknowledgeCounterValuesChanged)OTE(EVR:O.Data[10].1);
   // EVR
   11: NOP();
   12: XIC(EVR_System_Data.EVR.Bits.Requested.PLCLockout)OTE(EVR:O.Data[8].0);
   13: XIC(EVR_System_Data.EVR.Bits.Requested.GatewayRecipeLockout)OTE(EVR:O.Data[8].1);
   14: XIC(EVR_System_Data.EVR.Bits.Requested.AcknowledgeAllErrors)OTE(EVR:O.Data[8].2);
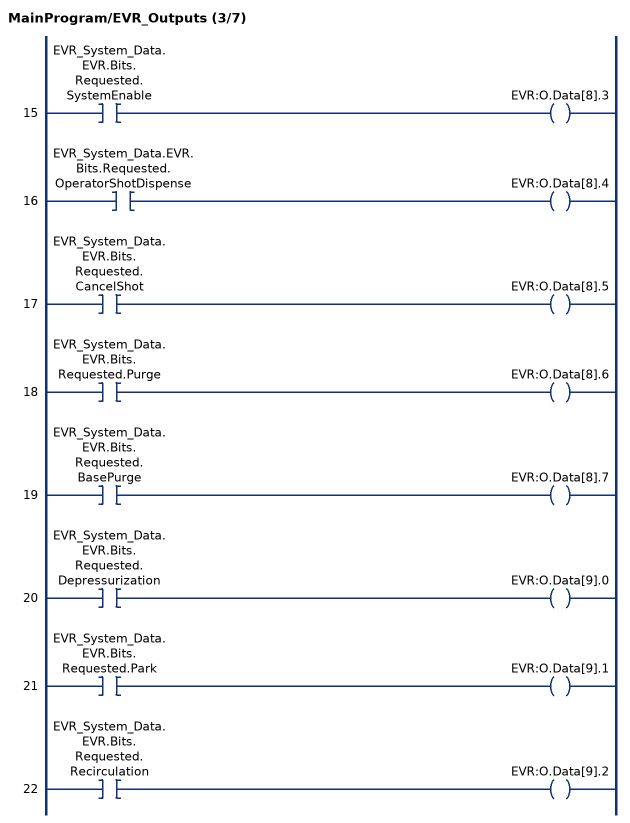
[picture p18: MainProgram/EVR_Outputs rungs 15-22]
   15: XIC(EVR_System_Data.EVR.Bits.Requested.SystemEnable)OTE(EVR:O.Data[8].3);
   16: XIC(EVR_System_Data.EVR.Bits.Requested.OperatorShotDispense)OTE(EVR:O.Data[8].4);
   17: XIC(EVR_System_Data.EVR.Bits.Requested.CancelShot)OTE(EVR:O.Data[8].5);
   18: XIC(EVR_System_Data.EVR.Bits.Requested.Purge)OTE(EVR:O.Data[8].6);
   19: XIC(EVR_System_Data.EVR.Bits.Requested.BasePurge)OTE(EVR:O.Data[8].7);
   20: XIC(EVR_System_Data.EVR.Bits.Requested.Depressurization)OTE(EVR:O.Data[9].0);
   21: XIC(EVR_System_Data.EVR.Bits.Requested.Park)OTE(EVR:O.Data[9].1);
   22: XIC(EVR_System_Data.EVR.Bits.Requested.Recirculation)OTE(EVR:O.Data[9].2);
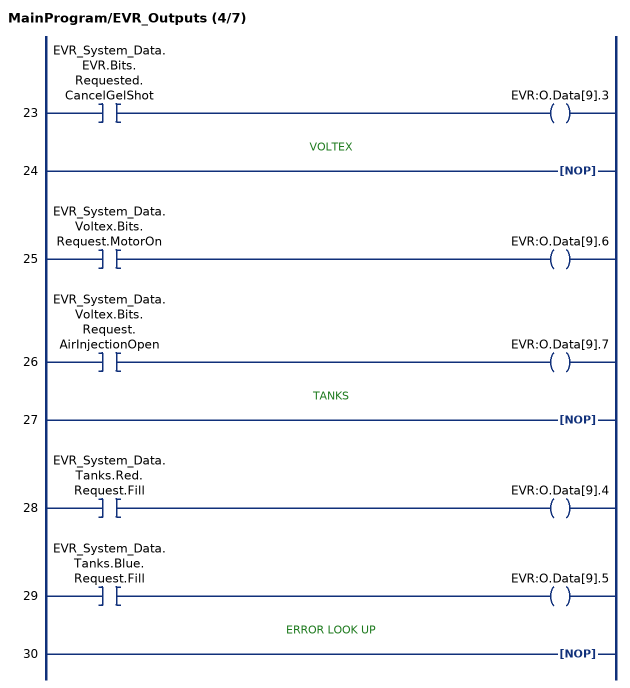
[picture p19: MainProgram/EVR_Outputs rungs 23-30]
   23: XIC(EVR_System_Data.EVR.Bits.Requested.CancelGelShot)OTE(EVR:O.Data[9].3);
   // VOLTEX
   24: NOP();
   25: XIC(EVR_System_Data.Voltex.Bits.Request.MotorOn)OTE(EVR:O.Data[9].6);
   26: XIC(EVR_System_Data.Voltex.Bits.Request.AirInjectionOpen)OTE(EVR:O.Data[9].7);
   // TANKS
   27: NOP();
   28: XIC(EVR_System_Data.Tanks.Red.Request.Fill)OTE(EVR:O.Data[9].4);
   29: XIC(EVR_System_Data.Tanks.Blue.Request.Fill)OTE(EVR:O.Data[9].5);
   // ERROR LOOK UP
   30: NOP();
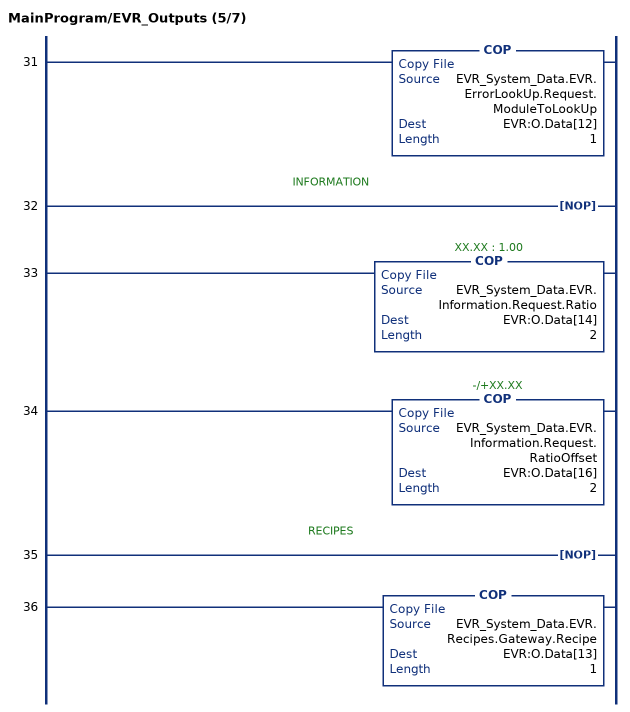
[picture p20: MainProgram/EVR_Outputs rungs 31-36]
   31: COP(EVR_System_Data.EVR.ErrorLookUp.Request.ModuleToLookUp,EVR:O.Data[12],1);
   // INFORMATION
   32: NOP();
   33: COP(EVR_System_Data.EVR.Information.Request.Ratio,EVR:O.Data[14],2);
   34: COP(EVR_System_Data.EVR.Information.Request.RatioOffset,EVR:O.Data[16],2);
   // RECIPES
   35: NOP();
   36: COP(EVR_System_Data.EVR.Recipes.Gateway.Recipe,EVR:O.Data[13],1);
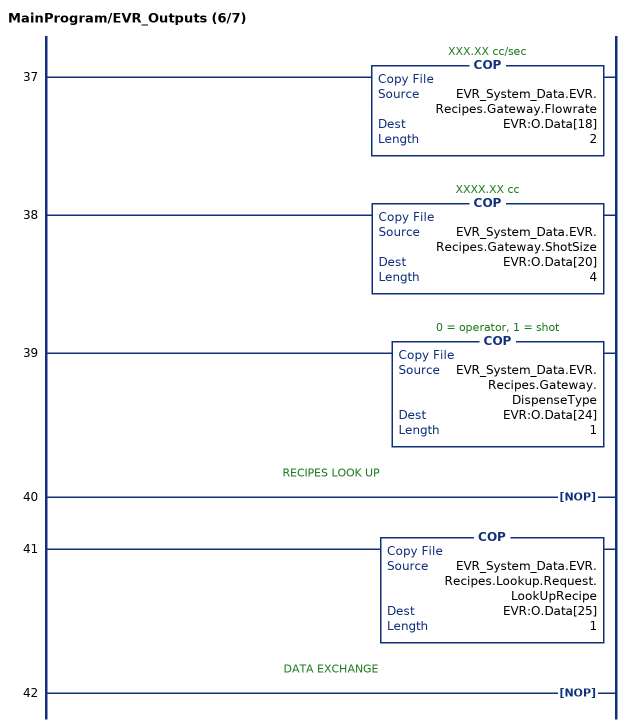
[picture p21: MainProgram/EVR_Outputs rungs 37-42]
   37: COP(EVR_System_Data.EVR.Recipes.Gateway.Flowrate,EVR:O.Data[18],2);
   38: COP(EVR_System_Data.EVR.Recipes.Gateway.ShotSize,EVR:O.Data[20],4);
   39: COP(EVR_System_Data.EVR.Recipes.Gateway.DispenseType,EVR:O.Data[24],1);
   // RECIPES LOOK UP
   40: NOP();
   41: COP(EVR_System_Data.EVR.Recipes.Lookup.Request.LookUpRecipe,EVR:O.Data[25],1);
   // DATA EXCHANGE
   42: NOP();
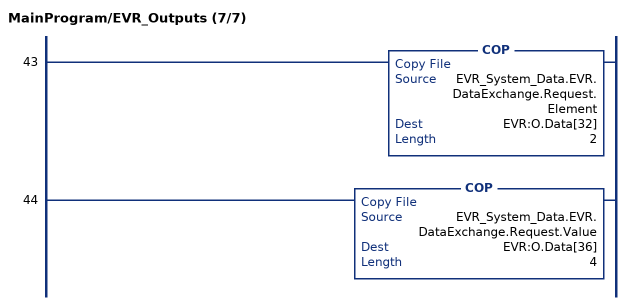
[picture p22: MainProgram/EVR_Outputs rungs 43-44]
   43: COP(EVR_System_Data.EVR.DataExchange.Request.Element,EVR:O.Data[32],2);
   44: COP(EVR_System_Data.EVR.DataExchange.Request.Value,EVR:O.Data[36],4);
END_ROUTINE
